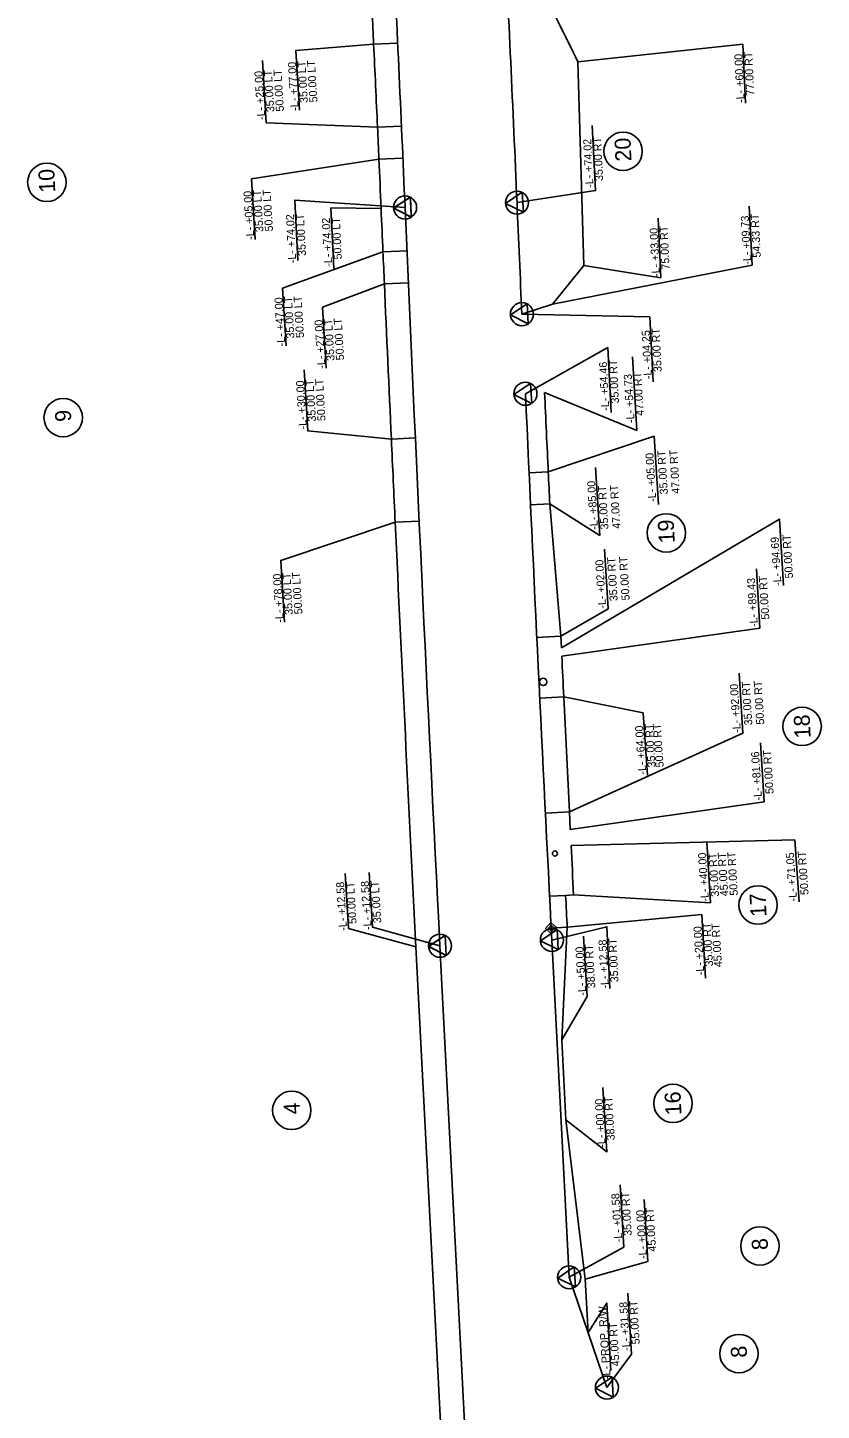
# Model space of a CAD drawing. Extents: x 2368169 to 2369183, y 801414 to 808542.
# Drawn here: x 2368608 to 2369104, y 802150 to 803014 of the extents above; entities that cross this region are included whole.
import ezdxf

# ---------------------------------------------------------------- set-up
doc = ezdxf.new("R2010")
doc.units = 0
for name, color, linetype in [('Prop Easement Construction', 7, 'Continuous'), ('Prop Easement Construction Station Offsets', 7, 'Continuous'), ('Prop Easement Permanent Drainage', 7, 'Continuous'), ('Prop Easement Permanent Drainage Station Offsets', 7, 'Continuous'), ('Prop Easement Permanent Drainage Utility', 7, 'Continuous'), ('Prop Easement Permanent Drainage Utility Station Offsets', 7, 'Continuous'), ('Prop Easement Permanent Utility', 7, 'Continuous'), ('Prop Easement Permanent Utility Station Offsets', 7, 'Continuous'), ('Prop Parcel Number CELL', 7, 'Continuous'), ('Prop Parcel Number Text', 7, 'Continuous'), ('Prop ROW Marker CELL', 7, 'Continuous'), ('Prop ROW Permanent Easement CELL', 7, 'Continuous'), ('Prop ROW RW Lines', 7, 'Continuous'), ('Prop ROW Station Offsets', 7, 'Continuous'), ('Scratch_Level_3', 7, 'Continuous')]:
    doc.layers.add(name, color=color, linetype=linetype)

msp = doc.modelspace()

# ---------------------------------------------------------------- linework, layer by layer
at = {"layer": 'Prop Easement Construction'}
for p, q in [((2368941.27, 802633.72), (2368934.36, 802716.41)), ((2368946.65, 802523.95), (2368943.1, 802595.79)), ((2368941.89, 802381.58), (2368945.29, 802451.85)), ((2368944.45, 802331.65), (2368941.89, 802381.58)), ((2368956.57, 802232.14), (2368944.45, 802331.65)), ((2368958.29, 802198.76), (2368956.57, 802232.14))]:
    msp.add_line(p, q, dxfattribs=at)
msp.add_arc((2425310.05, 805339.67), 56436.69, 182.593418, 182.643864, dxfattribs=at)
at = {"layer": 'Prop Easement Construction Station Offsets'}
for p, q in [((2368988.78, 802762.27), (2368986, 802808.23)), ((2368988.78, 802762.27), (2368931.16, 802786.01)), ((2368993.38, 802281.86), (2368995.73, 802243.17)), ((2368995.73, 802243.17), (2368956.57, 802232.14))]:
    msp.add_line(p, q, dxfattribs=at)
for points in [[(2368955.41, 802446.37), (2368957.7, 802408.62), (2368941.89, 802381.58)], [(2368967.53, 802351.8), (2368969.97, 802311.57), (2368944.45, 802331.65)], [(2368972.55, 802175.05), (2368970, 802217.07), (2368958.29, 802198.76)]]:
    msp.add_lwpolyline(points, dxfattribs=at)
at = {"layer": 'Prop Easement Permanent Drainage'}
for p, q in [((2368955.65, 802865.37), (2368952, 802992.53)), ((2368936.02, 802841.23), (2368955.65, 802865.37)), ((2368916.96, 802834.91), (2368936.02, 802841.23)), ((2368933.43, 802736.37), (2368921.44, 802735.82)), ((2368934.36, 802716.41), (2368922.37, 802715.85)), ((2368941.27, 802633.72), (2368926.29, 802633)), ((2368941.27, 802633.72), (2368941.62, 802626.42)), ((2368946.65, 802523.95), (2368931.66, 802523.2)), ((2368947.19, 802513.03), (2368946.65, 802523.95)), ((2368944.27, 802471.8), (2368934.28, 802471.3)), ((2368945.29, 802451.85), (2368935.3, 802451.33))]:
    msp.add_line(p, q, dxfattribs=at)
for centre, radius, start, end in [((2333618.27, 785468.75), 39440.53, 26.379142, 26.458672), ((2425310.05, 805339.67), 56436.69, 182.643864, 182.664151), ((2425310.05, 805339.67), 56438.69, 182.912674, 182.932961)]:
    msp.add_arc(centre, radius, start, end, dxfattribs=at)
at = {"layer": 'Prop Easement Permanent Drainage Station Offsets'}
for p, q in [((2369054.94, 803003.53), (2368952, 802992.53)), ((2369056.74, 802966.62), (2369054.94, 803003.53)), ((2369060.78, 802865.44), (2369058.98, 802902.34)), ((2369003.83, 802857.59), (2369002.02, 802894.78)), ((2369060.78, 802865.44), (2368936.02, 802841.23)), ((2369003.83, 802857.59), (2368955.65, 802865.37)), ((2368999.64, 802758.67), (2368933.43, 802736.37)), ((2368999.64, 802758.67), (2369002.21, 802716.03)), ((2368963.01, 802739.07), (2368965.57, 802696.65)), ((2368934.36, 802716.41), (2368965.57, 802696.65)), ((2369034.71, 802467.23), (2369032.41, 802505.13)), ((2368949.26, 802472.06), (2369034.71, 802467.23)), ((2368945.29, 802451.85), (2369029.29, 802459.87)), ((2369029.29, 802459.87), (2369031.68, 802420.18))]:
    msp.add_line(p, q, dxfattribs=at)
for points in [[(2369080.4, 802665.45), (2369077.89, 802706.89), (2368941.62, 802626.42)], [(2368968.59, 802688.16), (2368970.86, 802650.79), (2368941.27, 802633.72)], [(2369052.73, 802610.59), (2369055, 802573.13), (2368946.65, 802523.95)], [(2369066.04, 802567.01), (2369068.28, 802530.23), (2368947.19, 802513.03)]]:
    msp.add_lwpolyline(points, dxfattribs=at)
at = {"layer": 'Prop Easement Permanent Drainage Utility'}
for p, q in [((2368824.34, 803003.57), (2368839.32, 803004.28)), ((2368826.74, 802951.73), (2368841.72, 802952.41)), ((2368827.63, 802931.79), (2368842.62, 802932.45)), ((2368830.16, 802873.88), (2368845.14, 802874.54)), ((2368831.03, 802853.88), (2368846.02, 802854.54)), ((2368835.39, 802756.89), (2368850.37, 802757.58)), ((2368837.79, 802704.9), (2368852.77, 802705.6)), ((2368928.12, 802595.07), (2368943.1, 802595.79))]:
    msp.add_line(p, q, dxfattribs=at)
for centre, radius, start, end in [((2343687.36, 801815.32), 25165.05, 2.706404, 2.75185), ((2343687.36, 801815.32), 25165.05, 2.542799, 2.588245), ((2425310.05, 805339.67), 56533.69, 182.499822, 182.520109), ((2425310.05, 805339.67), 56533.69, 182.618504, 182.671252), ((2425310.05, 805339.67), 56433.69, 182.76109, 182.786891)]:
    msp.add_arc(centre, radius, start, end, dxfattribs=at)
at = {"layer": 'Prop Easement Permanent Drainage Utility Station Offsets'}
for p, q in [((2368792.41, 802839.36), (2368831.03, 802853.88)), ((2368794.71, 802801.15), (2368792.41, 802839.36)), ((2368943.1, 802595.79), (2368992.7, 802585.83)), ((2368995.34, 802546.99), (2368992.7, 802585.83))]:
    msp.add_line(p, q, dxfattribs=at)
for points in [[(2368778.02, 802962.27), (2368775.77, 802999.65), (2368824.34, 803003.57)], [(2368754.87, 802993.43), (2368757.21, 802954.52), (2368826.74, 802951.73)], [(2368750.27, 802881.64), (2368748, 802919.4), (2368827.63, 802931.79)], [(2368769.63, 802815.11), (2368767.46, 802851.19), (2368830.16, 802873.88)], [(2368780.87, 802800.07), (2368783.16, 802761.95), (2368835.39, 802756.89)], [(2368768.66, 802642.48), (2368766.34, 802681.06), (2368837.79, 802704.9)], [(2369063.44, 802675.71), (2369065.68, 802638.81), (2368941.87, 802621.18)]]:
    msp.add_lwpolyline(points, dxfattribs=at)
at = {"layer": 'Prop Easement Permanent Utility'}
for p, q in [((2368949.26, 802472.06), (2368944.27, 802471.8)), ((2368870.16, 802062.48), (2368850.79, 802439.57))]:
    msp.add_line(p, q, dxfattribs=at)
for centre, radius, start, end in [((2343687.36, 801815.32), 25165.05, 2.588245, 2.706404), ((2343687.36, 801815.32), 25165.05, 2.472411, 2.542799), ((2425310.05, 805339.67), 56533.69, 182.472411, 182.499822), ((2425310.05, 805339.67), 56533.69, 182.520109, 182.618504), ((2425310.05, 805339.67), 56533.69, 182.671252, 182.940485), ((2425310.05, 805339.67), 56433.69, 182.881178, 182.912674)]:
    msp.add_arc(centre, radius, start, end, dxfattribs=at)
at = {"layer": 'Prop Easement Permanent Utility Station Offsets'}
for p, q in [((2369087.51, 802506.58), (2368947.69, 802503.04)), ((2369090.14, 802467.74), (2369087.51, 802506.58))]:
    msp.add_line(p, q, dxfattribs=at)
for points in [[(2368799.52, 802863.43), (2368797.68, 802901.24), (2368828.98, 802900.9)], [(2368806.61, 802485.38), (2368808.67, 802451.13), (2368850.79, 802439.57)]]:
    msp.add_lwpolyline(points, dxfattribs=at)
at = {"layer": 'Prop Parcel Number CELL'}
for p, q in [((2368980.19, 802936.67), (2368980.19, 802936.67)), ((2368620.16, 802917.27), (2368620.16, 802917.27)), ((2368630.36, 802770.27), (2368630.36, 802770.27)), ((2369007.19, 802698.27), (2369007.19, 802698.27)), ((2369092.06, 802577.35), (2369092.06, 802577.35)), ((2369064.51, 802465.78), (2369064.51, 802465.78)), ((2368773.18, 802337.53), (2368773.18, 802337.53)), ((2369011.36, 802341.85), (2369011.36, 802341.85)), ((2369065.66, 802252.79), (2369065.66, 802252.79)), ((2369052.58, 802185.56), (2369052.58, 802185.56))]:
    msp.add_line(p, q, dxfattribs=at)
for centre in [(2368980.19, 802936.67), (2368620.16, 802917.27), (2368630.36, 802770.27), (2369007.19, 802698.27), (2369092.06, 802577.35), (2369064.51, 802465.78), (2369011.36, 802341.85), (2368773.18, 802337.53), (2369065.66, 802252.79), (2369052.58, 802185.56)]:
    msp.add_circle(centre, 12, dxfattribs=at)
at = {"layer": 'Prop ROW Marker CELL'}
for p, q in [((2368843.97, 802901.55), (2368843.97, 802901.55)), ((2368843.97, 802901.55), (2368843.97, 802901.55)), ((2368913.91, 802904.57), (2368913.91, 802904.57)), ((2368913.91, 802904.57), (2368913.91, 802904.57)), ((2368916.96, 802834.91), (2368916.96, 802834.91)), ((2368919.19, 802785.19), (2368919.19, 802785.19)), ((2368935.3, 802451.33), (2368935.3, 802451.33)), ((2368865.77, 802440.34), (2368865.77, 802440.34)), ((2368865.77, 802440.34), (2368865.77, 802440.34)), ((2368935.68, 802443.93), (2368935.68, 802443.93)), ((2368935.68, 802443.93), (2368935.68, 802443.93)), ((2368946.5, 802233.21), (2368946.5, 802233.21)), ((2368946.5, 802233.21), (2368946.5, 802233.21)), ((2368970.07, 802164.32), (2368970.07, 802164.32)), ((2368970.07, 802164.32), (2368970.07, 802164.32))]:
    msp.add_line(p, q, dxfattribs=at)
for points in [[(2368847.94, 802895.53), (2368836.78, 802901.12), (2368847.19, 802908)], [(2368847.85, 802895.47), (2368836.78, 802901.23), (2368847.29, 802907.96)], [(2368917.87, 802898.55), (2368906.72, 802904.14), (2368917.12, 802911.02)], [(2368917.87, 802898.55), (2368906.72, 802904.14), (2368917.12, 802911.02)], [(2368920.93, 802828.88), (2368909.77, 802834.47), (2368920.17, 802841.36)], [(2368923.16, 802779.17), (2368912, 802784.76), (2368922.4, 802791.65)], [(2368939.65, 802437.91), (2368928.49, 802443.5), (2368938.9, 802450.39)], [(2368939.65, 802437.91), (2368928.49, 802443.5), (2368938.9, 802450.39)], [(2368869.65, 802434.26), (2368858.58, 802440.02), (2368869.09, 802446.75)], [(2368869.74, 802434.32), (2368858.59, 802439.91), (2368868.99, 802446.8)], [(2368950.47, 802227.18), (2368939.32, 802232.77), (2368949.72, 802239.66)], [(2368950.47, 802227.18), (2368939.32, 802232.77), (2368949.72, 802239.66)], [(2368974.04, 802158.3), (2368962.88, 802163.89), (2368973.29, 802170.77)], [(2368974.04, 802158.3), (2368962.88, 802163.89), (2368973.29, 802170.77)]]:
    msp.add_lwpolyline(points, close=True, dxfattribs=at)
for centre in [(2368843.97, 802901.55), (2368913.91, 802904.57), (2368916.96, 802834.91), (2368919.19, 802785.19), (2368935.68, 802443.93), (2368865.77, 802440.34), (2368946.5, 802233.21), (2368970.07, 802164.32)]:
    msp.add_circle(centre, 7.2, dxfattribs=at)
at = {"layer": 'Prop ROW Permanent Easement CELL'}
for points in [[(2368935.52, 802447.74), (2368931.71, 802451.12), (2368935.08, 802454.93), (2368938.89, 802451.55)], [(2368935.41, 802449.54), (2368933.5, 802451.23), (2368935.19, 802453.13), (2368937.1, 802451.44)]]:
    msp.add_lwpolyline(points, close=True, dxfattribs=at)
at = {"layer": 'Prop ROW RW Lines'}
for p, q in [((2368885.14, 802063.25), (2368865.77, 802440.34)), ((2368946.5, 802233.21), (2368935.68, 802443.93)), ((2368970.07, 802164.32), (2368946.5, 802233.21))]:
    msp.add_line(p, q, dxfattribs=at)
for centre, radius, start, end in [((2343687.36, 801815.32), 25250.05, 2.472411, 2.872893), ((2343687.36, 801815.32), 25180.05, 2.472411, 2.872893), ((2425310.05, 805339.67), 56518.69, 182.472411, 182.940485), ((2425310.05, 805339.67), 56448.69, 182.472411, 182.543188), ((2425310.05, 805339.67), 56448.69, 182.593695, 182.940485)]:
    msp.add_arc(centre, radius, start, end, dxfattribs=at)
at = {"layer": 'Prop ROW Station Offsets'}
for p, q in [((2368996.98, 802833.24), (2368916.96, 802834.91)), ((2368996.98, 802833.24), (2368999.04, 802792.66)), ((2368970.68, 802814.01), (2368919.19, 802785.19)), ((2368970.68, 802814.01), (2368972.73, 802773.43))]:
    msp.add_line(p, q, dxfattribs=at)
for points in [[(2368960.89, 802952.71), (2368962.95, 802912.13), (2368913.91, 802904.57)], [(2368776.89, 802868.41), (2368775.05, 802906.21), (2368843.97, 802901.55)], [(2368821.59, 802486.15), (2368823.65, 802451.9), (2368865.77, 802440.34)], [(2368971.88, 802413.66), (2368970, 802452.22), (2368935.68, 802443.93)], [(2368978.41, 802290.91), (2368980.75, 802252.1), (2368946.5, 802233.21)], [(2368983.09, 802223.22), (2368985.37, 802185.27), (2368970.07, 802164.32)]]:
    msp.add_lwpolyline(points, dxfattribs=at)
at = {"layer": 'Scratch_Level_3'}
for centre, radius in [((2368930.29, 802605.16), 2.29), ((2368937.63, 802497.96), 1.58)]:
    msp.add_circle(centre, radius, dxfattribs=at)

# ---------------------------------------------------------------- texts
at = {"layer": 'Prop Easement Construction Station Offsets'}
for s, p in [('-L- +54.73', (2368987.42, 802767.04)), ('47.00 RT', (2368993.16, 802771.53)), ('38.00 RT', (2368962.89, 802413.92)), ('-L- +50.00', (2368957.16, 802409.32)), ('38.00 RT', (2368975.03, 802318.88)), ('-L- +00.00', (2368969.3, 802314.29)), ('45.00 RT', (2369000.86, 802249.41)), ('-L- +00.00', (2368995.13, 802244.81)), ('-L- PROP. R/W', (2368972.44, 802169.72)), ('45.00 RT', (2368977.97, 802177.72))]:
    msp.add_text(s, height=5, rotation=93.47163, dxfattribs=at).set_placement(p)
at = {"layer": 'Prop Easement Permanent Drainage Station Offsets'}
for s, rotation, p in [('-L- +60.00', 92.79291, (2369056.16, 802967.01)), ('77.00 RT', 92.79291, (2369062.19, 802971.56)), ('75.00 RT', 92.79291, (2369009.27, 802862.81)), ('-L- +09.73', 92.79291, (2369060.19, 802865.94)), ('54.33 RT', 92.79291, (2369066.23, 802870.37)), ('-L- +33.00', 92.79291, (2369003.23, 802858.27)), ('-L- +05.00', 93.44297, (2369000.96, 802717.76)), ('35.00 RT', 93.44297, (2369008.19, 802722.45)), ('47.00 RT', 93.44297, (2369015.68, 802722.9)), ('-L- +85.00', 93.44297, (2368964.53, 802700.33)), ('35.00 RT', 93.44297, (2368971.08, 802700.54)), ('47.00 RT', 93.44297, (2368978.57, 802700.99)), ('-L- +94.69', 93.47163, (2369079.16, 802665.29)), ('50.00 RT', 93.47163, (2369086.39, 802669.94)), ('35.00 RT', 93.47163, (2368976.82, 802655.75)), ('50.00 RT', 93.47163, (2368984.31, 802656.2)), ('-L- +02.00', 93.47163, (2368969.59, 802651.06)), ('35.00 RT', 93.47163, (2369060.96, 802578.19)), ('50.00 RT', 93.47163, (2369068.44, 802578.64)), ('-L- +92.00', 93.47163, (2369053.73, 802573.5)), ('-L- +81.06', 93.47163, (2369066.96, 802531.23)), ('50.00 RT', 93.47163, (2369074.23, 802535.31)), ('-L- +40.00', 93.47163, (2369033.81, 802468.02)), ('35.00 RT', 93.47163, (2369040.2, 802471.13)), ('45.00 RT', 93.47163, (2369045.93, 802471.4)), ('50.00 RT', 93.47163, (2369051.92, 802471.76)), ('-L- +20.00', 93.44297, (2369030.96, 802422.04)), ('35.00 RT', 93.44297, (2369036.47, 802427.56)), ('45.00 RT', 93.44297, (2369042.04, 802427.09))]:
    msp.add_text(s, height=5, rotation=rotation, dxfattribs=at).set_placement(p)
at = {"layer": 'Prop Easement Permanent Drainage Utility Station Offsets'}
for s, rotation, p in [('50.00 LT', 93.44297, (2368789.24, 802967.35)), ('-L- +25.00', 93.44297, (2368756.6, 802956.38)), ('35.00 LT', 93.44297, (2368762.32, 802961.27)), ('50.00 LT', 93.44297, (2368768.31, 802961.63)), ('-L- +77.00', 93.44297, (2368777.53, 802962.1)), ('35.00 LT', 93.44297, (2368783.25, 802966.99)), ('-L- +05.00', 93.44297, (2368749.78, 802881.47)), ('35.00 LT', 93.44297, (2368755.5, 802886.36)), ('50.00 LT', 93.44297, (2368761.48, 802886.72)), ('50.00 LT', 93.44297, (2368780.85, 802820.18)), ('-L- +47.00', 93.44297, (2368769.14, 802814.93)), ('35.00 LT', 93.44297, (2368774.86, 802819.82)), ('-L- +27.00', 93.44297, (2368794.22, 802800.97)), ('35.00 LT', 93.44297, (2368799.94, 802805.86)), ('50.00 LT', 93.44297, (2368805.93, 802806.22)), ('-L- +30.00', 93.44297, (2368782.6, 802763.02)), ('35.00 LT', 93.44297, (2368788.31, 802767.91)), ('50.00 LT', 93.44297, (2368794.3, 802768.27)), ('50.00 LT', 93.44297, (2368779.87, 802647.55)), ('-L- +78.00', 93.44297, (2368768.17, 802642.3)), ('35.00 LT', 93.44297, (2368773.88, 802647.19)), ('-L- +89.43', 93.47163, (2369064.38, 802639.64)), ('50.00 RT', 93.47163, (2369071.61, 802644.22)), ('35.00 RT', 93.87921, (2369000.57, 802551.92)), ('50.00 RT', 93.87921, (2369005.57, 802551.93)), ('-L- +64.00', 93.87921, (2368994.66, 802547.43))]:
    msp.add_text(s, height=5, rotation=rotation, dxfattribs=at).set_placement(p)
at = {"layer": 'Prop Easement Permanent Utility Station Offsets'}
for s, rotation, p in [('-L- +74.02', 92.79291, (2368798.42, 802864.64)), ('50.00 LT', 92.79291, (2368804.46, 802869.2)), ('-L- +71.05', 93.87921, (2369088.86, 802468.21)), ('50.00 RT', 93.87921, (2369096.1, 802472.25)), ('-L- +12.58', 93.44297, (2368807.67, 802449.84)), ('50.00 LT', 93.44297, (2368813.67, 802454.15))]:
    msp.add_text(s, height=5, rotation=rotation, dxfattribs=at).set_placement(p)
at = {"layer": 'Prop Parcel Number Text'}
for s, rotation, p in [('20', 92.79291, (2368985.48, 802930.5)), ('10', 92.79291, (2368625.46, 802911.03)), ('9', 92.79291, (2368635.47, 802767.91)), ('19', 92.79291, (2369012.5, 802691.98)), ('18', 92.79291, (2369097.41, 802570.14)), ('17', 92.79291, (2369069.87, 802458.58)), ('16', 92.79291, (2369016.72, 802334.65)), ('4', 92.79291, (2368778.29, 802335.21)), ('8', 93.44297, (2369070.81, 802250.49)), ('8', 93.44297, (2369057.73, 802183.26))]:
    msp.add_text(s, height=10, rotation=rotation, dxfattribs=at).set_placement(p)
at = {"layer": 'Prop ROW Station Offsets'}
for s, rotation, p in [('-L- +74.02', 92.79291, (2368961.7, 802913.93)), ('35.00 RT', 92.79291, (2368967.75, 802918.2)), ('-L- +74.02', 92.79291, (2368776.02, 802866.83)), ('35.00 LT', 92.79291, (2368782.06, 802871.39)), ('-L- +04.25', 92.79291, (2368998.26, 802794.41)), ('35.00 RT', 92.79291, (2369004.3, 802798.85)), ('-L- +54.46', 92.79291, (2368971.62, 802774.67)), ('35.00 RT', 92.79291, (2368977.65, 802779.19)), ('-L- +12.58', 93.44297, (2368823.12, 802450.33)), ('35.00 LT', 93.44297, (2368829.12, 802454.63)), ('-L- +12.58', 92.79278, (2368971.25, 802413.68)), ('35.00 RT', 92.79278, (2368977.32, 802417.62)), ('-L- +01.58', 93.44297, (2368979.64, 802255.23)), ('35.00 RT', 93.44297, (2368985.66, 802259.24)), ('-L- +31.58', 93.44297, (2368984.62, 802187.4)), ('55.00 RT', 93.44297, (2368990.64, 802191.41))]:
    msp.add_text(s, height=5, rotation=rotation, dxfattribs=at).set_placement(p)

doc.saveas('drawing.dxf')
